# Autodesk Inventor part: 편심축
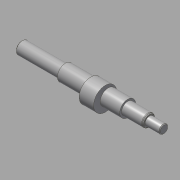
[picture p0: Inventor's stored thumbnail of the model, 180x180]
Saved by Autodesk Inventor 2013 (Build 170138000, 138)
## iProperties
Created: 2016-05
Part Number: 편심축
Document SubType Name: Modeling
Designer: mduedu
Density: 7.86 g/cm^3
Material: 강철, 연강
Author: mduedu
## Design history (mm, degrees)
sketch "스케치1"
  geometry: L1 (-38, 11)-(-38, 8.5); L2 (48, 11)-(48, 8.5); L3 (-98, 0)-(98, 0); L4 (-38, 11)-(48, 11); L5 (48, 11)-(48, 8.5); L6 (-38, 11)-(-38, 8.5); L7 (-38, 8.5)-(-98, 8.5); L8 (-98, 8.5)-(-98, 0); L9 (48, 8.5)-(78, 8.5); L10 (98, 6)-(98, 0); L11 (78, 8.5)-(78, 6); L12 (78, 6)-(98, 6); 1 further point
  constraints: 24 end point, 9 perpendicular, 2 midpoint, 1 collinear, 1 horizontal
  dimensions: "d0" = 22 diameter of L4 L3; "d1" = 17 diameter of L7 L3; "d2" = 60 distance between parallel lines of L8 L1; "d3" = 50 distance between parallel lines of L10 L2; "d4" = 12 diameter of L12 L3; "d5" = 20 distance between parallel lines of L10 L11; "d29" = 86 distance of L1.start L2.start
revolve "회전1" stored, may be unused: angle "d6" = 90 deg
node "작업 평면7"
node "작업 평면9"
sketch "스케치2"
  geometry: C1 r 11 at (0, 0); C2 r 16 at (0, -4); C3 r 11 at (0, 0); 2 further points
  constraints: 3 centre point, 2 coincident, 1 concentric, 1 vertical alignment
  dimensions: "d9" = 4 distance of point (0, 0) C2.centre; "d10" = 32 diameter of C2
extrude "돌출1" join sketch "스케치2" stored distance "d11" = 20; taper "d12" = 0 deg
chamfer "모따기2" distance "d32" = 1; stored, may be unused: second distance "d33" = 2, angle "d34" = 45 deg
node "작업 평면4"
sketch "스케치4"
  geometry: L1 (-5, 2)-(5, 2); L2 (5, -2)-(-5, -2); L3 (-10, -5)-(-10, 5) reference; A1 r 2 centre (5, 0) between (5, -2) and (5, 2); A2 r 2 centre (-5, 0) between (-5, 2) and (-5, -2); 2 further points
  constraints: 4 end point, 4 point on circle, 4 tangent, 2 centre point, 2 horizontal alignment, 1 midpoint, 1 parallel
  dimensions: "d20" = 4 distance between parallel lines of L2 L1; "d21" = 14 dimension on A1 A2; "d35" = 3 distance edge to line of A2 L3
extrude "돌출3" cut sketch "스케치4" distance "d23" = 2.5; taper "d24" = 0 deg
node "작업 평면5"
sketch "스케치5"
  geometry: L1 (30, 2.5)-(12.5, 2.5); L2 (12.5, -2.5)-(30, -2.5); L3 (30, 7.5)-(30, -7.5) reference; A1 r 2.5 centre (12.5, 0) between (12.5, 2.5) and (12.5, -2.5); 2 further points
  constraints: 4 end point, 2 point on circle, 2 point on line, 2 tangent, 1 centre point, 1 horizontal, 1 horizontal alignment, 1 midpoint
  dimensions: "d25" = 5 distance between parallel lines of L2 L1; "d36" = 20 dimension on A1 L3
extrude "돌출4" cut sketch "스케치5" distance "d27" = 3; taper "d28" = 0 deg
chamfer "모따기3" distance "d37" = 1.82; stored, may be unused: second distance "d38" = 2, angle "d39" = 30 deg
fillet "모깎기1" dims "d40" = 2, "d41" = 0.5
node "솔리드1"
other parameters: "d31" = -37
